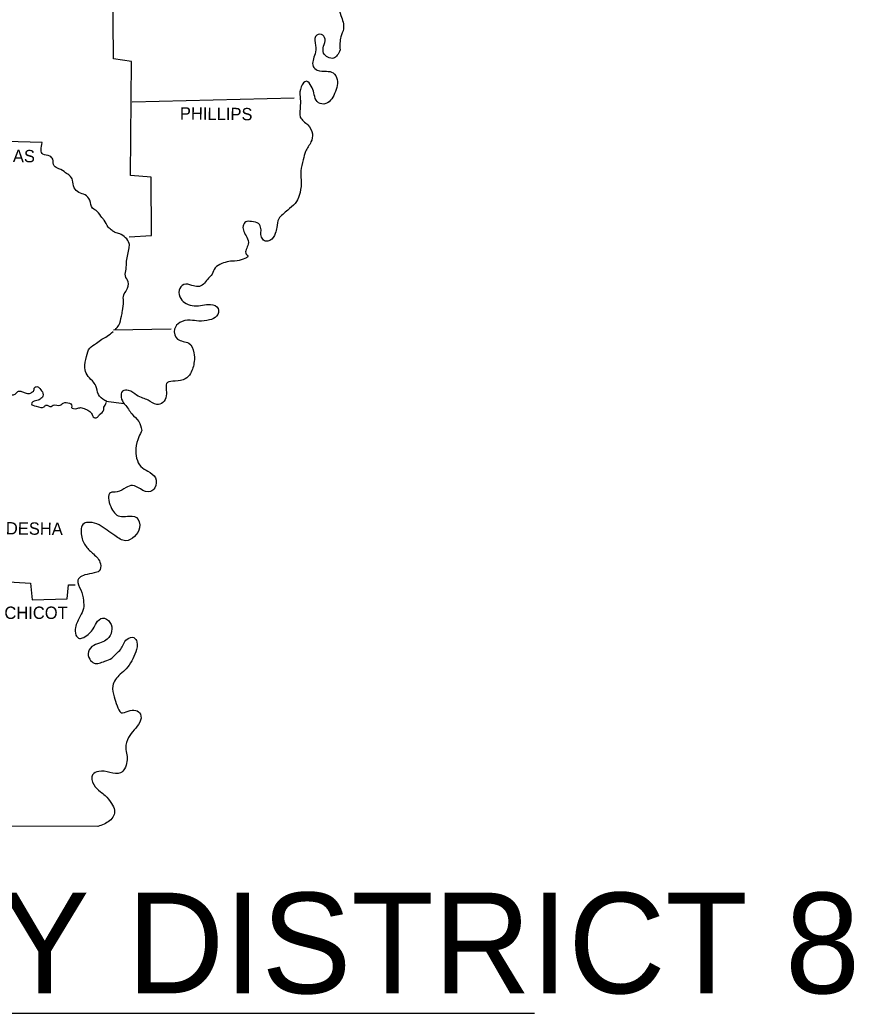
# Model space of a CAD drawing. Extents: x 1373862 to 1376999, y 1168398 to 1170455.
# Drawn here: x 1376569.3 to 1376859.3, y 1169681.4 to 1170026.9 of the extents above; entities that cross this region are included whole.
import ezdxf

# ---------------------------------------------------------------- set-up
doc = ezdxf.new("R2010")
doc.units = 0
doc.layers.add('R_Draft', color=7, linetype='Continuous')

msp = doc.modelspace()

# ---------------------------------------------------------------- linework, layer by layer
at = {"layer": 'R_Draft'}
for p, q in [((1376601.9, 1169919.1), (1376621.9, 1169919.4)), ((1376605.5, 1169893.3), (1376599.2, 1169894.1)), ((1376086.96, 1169681.4), (1376748.18, 1169681.4))]:
    msp.add_line(p, q, dxfattribs=at)
for points in [[(1376607.3, 1169951.4), (1376615.1, 1169951.9), (1376615, 1169972.2), (1376607.7, 1169972.7), (1376608.1, 1170012.4), (1376601.8, 1170013.3), (1376601.6, 1170040), (1376686.9, 1170040.6)], [(1376608.3, 1169998.3), (1376664.7, 1169999.7)], [(1376577, 1169984.2), (1376539.2, 1169985.2), (1376539, 1169972.9), (1376462.5, 1169972.6)], [(1376559.6, 1169831.7), (1376573, 1169830.9), (1376573.6, 1169825.1), (1376585.7, 1169825.5), (1376586.2, 1169830.4), (1376588.5, 1169830.4)], [(1376596.4, 1169746.3), (1376229.9, 1169746.9), (1376229.7, 1169827.8)]]:
    msp.add_lwpolyline(points, dxfattribs=at)
for points in [[(1376724, 1170115.5), (1376724.4, 1170112.6), (1376722.7, 1170109.5), (1376722.1, 1170106.4), (1376722.4, 1170103.3), (1376719.2, 1170101.6), (1376716.4, 1170099.6), (1376718, 1170097.2), (1376721, 1170095), (1376724, 1170093.3), (1376725.9, 1170091.6), (1376726.4, 1170087.5), (1376726.9, 1170084.9), (1376727.9, 1170081.3), (1376728.3, 1170078.8), (1376726.5, 1170075.8), (1376724.4, 1170075.2), (1376722.2, 1170075.9), (1376719.6, 1170076.1), (1376717.5, 1170074.1), (1376716, 1170071.3), (1376714.5, 1170068.5), (1376713.4, 1170066.1), (1376712.3, 1170063.5), (1376710.1, 1170060.5), (1376707.4, 1170060), (1376704.2, 1170059.2), (1376702.3, 1170057), (1376702.6, 1170053.3), (1376704.4, 1170050.8), (1376705.8, 1170047.7), (1376706.8, 1170045), (1376706.3, 1170041.6), (1376704.9, 1170039.1), (1376703.1, 1170037.6), (1376702.3, 1170034.4), (1376701, 1170032), (1376699.8, 1170031.2), (1376697.4, 1170031.4), (1376694.8, 1170031.9), (1376692.6, 1170031.7), (1376690.5, 1170030.6), (1376688.4, 1170031.3), (1376686.2, 1170033.7), (1376684.4, 1170035.5), (1376682.4, 1170036.2), (1376680.3, 1170035.1), (1376679.9, 1170031.8), (1376680.9, 1170028.4), (1376681.8, 1170023.8), (1376680.9, 1170021), (1376680.6, 1170016.4)], [(1376724, 1170115.5), (1376724.4, 1170112.6), (1376722.7, 1170109.5), (1376722.1, 1170106.4), (1376722.4, 1170103.3), (1376719.2, 1170101.6), (1376716.4, 1170099.6), (1376718, 1170097.2), (1376721, 1170095), (1376724, 1170093.3), (1376725.9, 1170091.6), (1376726.4, 1170087.5), (1376726.9, 1170084.9), (1376727.9, 1170081.3), (1376728.3, 1170078.8), (1376726.5, 1170075.8), (1376724.4, 1170075.2), (1376722.2, 1170075.9), (1376719.6, 1170076.1), (1376717.5, 1170074.1), (1376716, 1170071.3), (1376714.5, 1170068.5), (1376713.4, 1170066.1), (1376712.3, 1170063.5), (1376710.1, 1170060.5), (1376707.4, 1170060), (1376704.2, 1170059.2), (1376702.3, 1170057), (1376702.6, 1170053.3), (1376704.4, 1170050.8), (1376705.8, 1170047.7), (1376706.8, 1170045), (1376706.3, 1170041.6), (1376704.9, 1170039.1), (1376703.1, 1170037.6), (1376702.3, 1170034.4), (1376701, 1170032), (1376699.8, 1170031.2), (1376697.4, 1170031.4), (1376694.8, 1170031.9), (1376692.6, 1170031.7), (1376690.5, 1170030.6), (1376688.4, 1170031.3), (1376686.2, 1170033.7), (1376684.4, 1170035.5), (1376682.4, 1170036.2), (1376680.3, 1170035.1), (1376679.9, 1170031.8), (1376680.9, 1170028.4), (1376681.8, 1170023.8), (1376680.9, 1170021), (1376680.6, 1170016.4)], [(1376680.6, 1170016.4), (1376678.3, 1170013.5), (1376674.9, 1170015.3), (1376674.9, 1170017.7), (1376675.4, 1170020.2), (1376674.2, 1170021.8), (1376672.1, 1170021.1), (1376672.1, 1170018), (1376671.9, 1170015), (1376671.3, 1170010.7), (1376672.7, 1170009.4), (1376675.9, 1170009), (1376678.2, 1170008.4), (1376679.6, 1170006.1), (1376679.5, 1170003.3), (1376678.4, 1170000.6), (1376676.8, 1169998.4), (1376674.3, 1169997.6), (1376672.3, 1169998.9), (1376671.5, 1170001.5), (1376670.6, 1170003.8), (1376668.9, 1170005.5), (1376667.1, 1170003.6), (1376666.7, 1170000.1), (1376666.8, 1169997.1), (1376666.8, 1169993), (1376669.4, 1169990.3), (1376671, 1169987.2), (1376670.5, 1169984.4), (1376668.6, 1169981.1), (1376667.8, 1169978.2), (1376667, 1169974.3), (1376667.1, 1169970), (1376666.4, 1169965.8), (1376665, 1169963), (1376662.4, 1169960.7), (1376660.7, 1169959.2), (1376659.3, 1169957.7), (1376658.6, 1169954.7), (1376658.1, 1169952.6), (1376656.2, 1169950.1), (1376654.7, 1169949.9), (1376653.5, 1169950.9), (1376653.1, 1169952.6), (1376653.1, 1169954.3), (1376652.3, 1169956), (1376649.8, 1169956.7), (1376647.8, 1169956.6), (1376646.9, 1169955.2), (1376648.2, 1169951.3), (1376648.7, 1169948.8), (1376648, 1169945.4), (1376648.4, 1169945), (1376644.8, 1169943.1), (1376641.9, 1169942.8), (1376639.5, 1169942.1), (1376637.2, 1169940.6), (1376636.1, 1169938.4), (1376634.5, 1169936.6), (1376633.1, 1169934.9), (1376631.2, 1169934.1), (1376629.1, 1169934.5), (1376626.3, 1169934.8), (1376624.7, 1169932.8), (1376625.2, 1169929.9), (1376627.1, 1169928.2), (1376629.9, 1169927.4), (1376632.8, 1169927.6), (1376635.6, 1169927.9), (1376638.2, 1169926.5), (1376637.7, 1169923.8), (1376635.2, 1169922.5), (1376631.5, 1169922.1), (1376628.5, 1169922.4), (1376624.9, 1169921.6), (1376623.1, 1169919.3), (1376624.1, 1169915.8), (1376628, 1169914.4), (1376629.8, 1169911.1), (1376629.9, 1169908), (1376628.6, 1169903.9), (1376626.8, 1169902), (1376623.3, 1169901.2), (1376620.6, 1169900.7), (1376620.2, 1169896.1), (1376619, 1169893.8), (1376616.9, 1169893.1), (1376613.9, 1169894.6), (1376612.1, 1169895.3), (1376609.9, 1169896.3), (1376607.1, 1169898), (1376605, 1169897.7), (1376605.6, 1169893.3), (1376605.8, 1169893.1), (1376608.2, 1169889.8), (1376610.6, 1169887.2), (1376611.7, 1169884.1)], [(1376680.6, 1170016.4), (1376678.3, 1170013.5), (1376674.9, 1170015.3), (1376674.9, 1170017.7), (1376675.4, 1170020.2), (1376674.2, 1170021.8), (1376672.1, 1170021.1), (1376672.1, 1170018), (1376671.9, 1170015), (1376671.3, 1170010.7), (1376672.7, 1170009.4), (1376675.9, 1170009), (1376678.2, 1170008.4), (1376679.6, 1170006.1), (1376679.5, 1170003.3), (1376678.4, 1170000.6), (1376676.8, 1169998.4), (1376674.3, 1169997.6), (1376672.3, 1169998.9), (1376671.5, 1170001.5), (1376670.6, 1170003.8), (1376668.9, 1170005.5), (1376667.1, 1170003.6), (1376666.7, 1170000.1), (1376666.8, 1169997.1), (1376666.8, 1169993), (1376669.4, 1169990.3), (1376671, 1169987.2), (1376670.5, 1169984.4), (1376668.6, 1169981.1), (1376667.8, 1169978.2), (1376667, 1169974.3), (1376667.1, 1169970), (1376666.4, 1169965.8), (1376665, 1169963), (1376662.4, 1169960.7), (1376660.7, 1169959.2), (1376659.3, 1169957.7), (1376658.6, 1169954.7), (1376658.1, 1169952.6), (1376656.2, 1169950.1), (1376654.7, 1169949.9), (1376653.5, 1169950.9), (1376653.1, 1169952.6), (1376653.1, 1169954.3), (1376652.3, 1169956), (1376649.8, 1169956.7), (1376647.8, 1169956.6), (1376646.9, 1169955.2), (1376648.2, 1169951.3), (1376648.7, 1169948.8), (1376648, 1169945.4), (1376648.4, 1169945), (1376644.8, 1169943.1), (1376641.9, 1169942.8), (1376639.5, 1169942.1), (1376637.2, 1169940.6), (1376636.1, 1169938.4), (1376634.5, 1169936.6), (1376633.1, 1169934.9), (1376631.2, 1169934.1), (1376629.1, 1169934.5), (1376626.3, 1169934.8), (1376624.7, 1169932.8), (1376625.2, 1169929.9), (1376627.1, 1169928.2), (1376629.9, 1169927.4), (1376632.8, 1169927.6), (1376635.6, 1169927.9), (1376638.2, 1169926.5), (1376637.7, 1169923.8), (1376635.2, 1169922.5), (1376631.5, 1169922.1), (1376628.5, 1169922.4), (1376624.9, 1169921.6), (1376623.1, 1169919.3), (1376624.1, 1169915.8), (1376628, 1169914.4), (1376629.8, 1169911.1), (1376629.9, 1169908), (1376628.6, 1169903.9), (1376626.8, 1169902), (1376623.3, 1169901.2), (1376620.6, 1169900.7), (1376620.2, 1169896.1), (1376619, 1169893.8), (1376616.9, 1169893.1), (1376613.9, 1169894.6), (1376612.1, 1169895.3), (1376609.9, 1169896.3), (1376607.1, 1169898), (1376605, 1169897.7), (1376605.6, 1169893.3), (1376605.8, 1169893.1), (1376608.2, 1169889.8), (1376610.6, 1169887.2), (1376611.7, 1169884.1)], [(1376602.4, 1169919.1), (1376603.7, 1169920.7), (1376604.6, 1169923.8), (1376605, 1169925.7), (1376605.3, 1169929), (1376605.4, 1169931.2), (1376606.4, 1169932.8), (1376606.9, 1169935.8), (1376606, 1169937.8), (1376606.2, 1169940.2), (1376606.4, 1169942.9), (1376606.8, 1169945.3), (1376607.3, 1169947.6), (1376607.3, 1169949.1), (1376606, 1169951.1), (1376604, 1169952.4), (1376602.4, 1169952.9), (1376601.4, 1169953.6), (1376600, 1169954.8), (1376598.6, 1169957.2), (1376597.8, 1169958.1), (1376596.2, 1169960.2), (1376594.6, 1169961.4), (1376593.6, 1169964.1), (1376592, 1169966), (1376589.8, 1169966.8), (1376588.2, 1169968.5), (1376587.6, 1169971.1), (1376586.6, 1169972.7), (1376585.2, 1169973.7), (1376582.9, 1169975.1), (1376581.2, 1169976.1), (1376580.7, 1169978.4), (1376579.7, 1169979.5), (1376577.3, 1169980.1), (1376577, 1169984.2)], [(1376539, 1169932.5), (1376540.5, 1169931.5), (1376542.6, 1169931.6), (1376544, 1169932.2), (1376545.1, 1169932.1), (1376546.6, 1169931.2), (1376547.6, 1169930), (1376548.3, 1169929.1), (1376548.8, 1169927.7), (1376548.8, 1169926.4), (1376549.3, 1169924.6), (1376549.9, 1169923.9), (1376550.7, 1169922.6), (1376551.2, 1169921.4), (1376551.5, 1169920.6), (1376552.6, 1169919.3), (1376553.6, 1169919.4), (1376554.5, 1169919.3), (1376555.7, 1169918.6), (1376557.5, 1169917.2), (1376557.8, 1169916.8), (1376559, 1169914.2), (1376559.2, 1169912.6), (1376559.4, 1169910.5), (1376559.8, 1169908.5), (1376560.6, 1169906.3), (1376561, 1169904.8), (1376561.9, 1169902.7), (1376562.5, 1169901.3), (1376563.3, 1169899.5), (1376564.5, 1169897.5), (1376565, 1169896.3), (1376566.7, 1169896.4), (1376567.9, 1169896.9), (1376568.8, 1169897.7), (1376569.9, 1169897.6), (1376571.1, 1169897.2), (1376572.7, 1169896.9), (1376573.7, 1169897.5), (1376574.2, 1169897.9), (1376574.3, 1169898.8), (1376575.2, 1169899.3), (1376576.2, 1169898.6), (1376577.3, 1169897), (1376577.3, 1169896), (1376576.9, 1169895.4), (1376575.6, 1169894.6), (1376573.8, 1169894), (1376573.3, 1169893.3), (1376575, 1169892.5), (1376577.7, 1169892.3), (1376578.4, 1169892.9), (1376580.2, 1169892.4), (1376580.9, 1169892.9), (1376583.3, 1169892.8), (1376584.4, 1169893.6), (1376586.6, 1169893.5), (1376587.3, 1169893), (1376587.3, 1169892.1), (1376589.1, 1169891.7), (1376590.4, 1169892), (1376592.1, 1169891.5), (1376593.6, 1169890.7), (1376594.4, 1169889.6), (1376595.4, 1169888.4), (1376596.3, 1169888.7), (1376597, 1169889.6), (1376598.5, 1169891.2), (1376598.5, 1169892.2), (1376598.9, 1169892.9), (1376599.4, 1169893.9)], [(1376599.5, 1169894.2), (1376598.8, 1169894.5), (1376596.6, 1169896.6), (1376595.7, 1169899.6), (1376594.5, 1169901.3), (1376592.7, 1169903.4), (1376591.9, 1169905.8), (1376592.5, 1169909.8), (1376593.6, 1169912.7), (1376595.9, 1169914.4), (1376597.8, 1169915.8), (1376599.6, 1169916.8), (1376601.7, 1169918.5)], [(1376611.7, 1169884.1), (1376610.7, 1169881.8), (1376609.6, 1169877.8), (1376609.9, 1169874.4), (1376611.4, 1169871.5), (1376613.8, 1169869.9), (1376616.4, 1169867.6), (1376616.2, 1169864.1), (1376614.7, 1169862.8), (1376611.2, 1169863.7), (1376608.5, 1169864.9), (1376606.2, 1169864.2), (1376603.1, 1169862.7), (1376600.8, 1169862.4), (1376600.9, 1169857.6), (1376604, 1169854.2), (1376606.7, 1169854.2), (1376609.8, 1169853.8), (1376610.9, 1169850.2), (1376609.1, 1169847.2), (1376606.1, 1169845.7), (1376602.3, 1169847.5), (1376599.6, 1169849.4), (1376596.9, 1169851.2), (1376593.5, 1169852.1), (1376591.6, 1169851.7), (1376590.7, 1169847.5), (1376592.3, 1169843.7), (1376594.9, 1169841.1), (1376597.3, 1169837.7), (1376596.9, 1169835.2), (1376595.1, 1169834.5), (1376591.9, 1169833.8), (1376590, 1169832.8), (1376589.5, 1169832), (1376590.5, 1169828.6), (1376591.4, 1169824.9), (1376591.4, 1169822.1), (1376590.3, 1169819.5), (1376588.6, 1169815.5), (1376588.8, 1169812.9), (1376590, 1169811.7), (1376591.5, 1169812.1), (1376593.5, 1169813.5), (1376594.8, 1169815.1), (1376595.9, 1169817.1), (1376598, 1169818.8), (1376600.6, 1169817.3), (1376601.2, 1169814.2), (1376599.7, 1169811.5), (1376597.6, 1169810.3), (1376595, 1169809.3), (1376593.1, 1169807.1), (1376593.6, 1169804.5), (1376595.1, 1169803.1), (1376598.8, 1169803.8), (1376601.3, 1169804.9), (1376602.7, 1169806.3), (1376604.4, 1169808), (1376605.3, 1169809.7), (1376606.6, 1169811.5), (1376608.9, 1169812), (1376610, 1169810.5), (1376609.6, 1169807.1), (1376608.2, 1169803.9), (1376606.3, 1169801.2), (1376604.2, 1169799.3), (1376601.6, 1169795.2), (1376602.1, 1169791.4), (1376603.1, 1169788.3), (1376604.5, 1169785.9), (1376606.9, 1169786.4), (1376609.6, 1169786.7), (1376611.2, 1169785.4), (1376611, 1169782.6), (1376609, 1169779.9), (1376607.1, 1169777.3), (1376606.1, 1169773.7), (1376606.5, 1169771.2), (1376606.5, 1169768.9), (1376605.7, 1169766.4), (1376604.3, 1169765), (1376600.6, 1169765.1), (1376596.7, 1169765.5), (1376594.6, 1169764.3), (1376595, 1169760.9), (1376597.3, 1169758.4), (1376598.9, 1169757.1), (1376601.2, 1169754.3), (1376602.2, 1169752), (1376601.9, 1169750), (1376600.5, 1169748.3), (1376596.4, 1169746.3)], [(1376611.7, 1169884.1), (1376610.7, 1169881.8), (1376609.6, 1169877.8), (1376609.9, 1169874.4), (1376611.4, 1169871.5), (1376613.8, 1169869.9), (1376616.4, 1169867.6), (1376616.2, 1169864.1), (1376614.7, 1169862.8), (1376611.2, 1169863.7), (1376608.5, 1169864.9), (1376606.2, 1169864.2), (1376603.1, 1169862.7), (1376600.8, 1169862.4), (1376600.9, 1169857.6), (1376604, 1169854.2), (1376606.7, 1169854.2), (1376609.8, 1169853.8), (1376610.9, 1169850.2), (1376609.1, 1169847.2), (1376606.1, 1169845.7), (1376602.3, 1169847.5), (1376599.6, 1169849.4), (1376596.9, 1169851.2), (1376593.5, 1169852.1), (1376591.6, 1169851.7), (1376590.7, 1169847.5), (1376592.3, 1169843.7), (1376594.9, 1169841.1), (1376597.3, 1169837.7), (1376596.9, 1169835.2), (1376595.1, 1169834.5), (1376591.9, 1169833.8), (1376590, 1169832.8), (1376589.5, 1169832), (1376590.5, 1169828.6), (1376591.4, 1169824.9), (1376591.4, 1169822.1), (1376590.3, 1169819.5), (1376588.6, 1169815.5), (1376588.8, 1169812.9), (1376590, 1169811.7), (1376591.5, 1169812.1), (1376593.5, 1169813.5), (1376594.8, 1169815.1), (1376595.9, 1169817.1), (1376598, 1169818.8), (1376600.6, 1169817.3), (1376601.2, 1169814.2), (1376599.7, 1169811.5), (1376597.6, 1169810.3), (1376595, 1169809.3), (1376593.1, 1169807.1), (1376593.6, 1169804.5), (1376595.1, 1169803.1), (1376598.8, 1169803.8), (1376601.3, 1169804.9), (1376602.7, 1169806.3), (1376604.4, 1169808), (1376605.3, 1169809.7), (1376606.6, 1169811.5), (1376608.9, 1169812), (1376610, 1169810.5), (1376609.6, 1169807.1), (1376608.2, 1169803.9), (1376606.3, 1169801.2), (1376604.2, 1169799.3), (1376601.6, 1169795.2), (1376602.1, 1169791.4), (1376603.1, 1169788.3), (1376604.5, 1169785.9), (1376606.9, 1169786.4), (1376609.6, 1169786.7), (1376611.2, 1169785.4), (1376611, 1169782.6), (1376609, 1169779.9), (1376607.1, 1169777.3), (1376606.1, 1169773.7), (1376606.5, 1169771.2), (1376606.5, 1169768.9), (1376605.7, 1169766.4), (1376604.3, 1169765), (1376600.6, 1169765.1), (1376596.7, 1169765.5), (1376594.6, 1169764.3), (1376595, 1169760.9), (1376597.3, 1169758.4), (1376598.9, 1169757.1), (1376601.2, 1169754.3), (1376602.2, 1169752), (1376601.9, 1169750), (1376600.5, 1169748.3), (1376596.4, 1169746.3)]]:
    msp.add_spline(points, degree=3, dxfattribs=at)

# ---------------------------------------------------------------- texts
for s, rotation, p in [('PHILLIPS', 359.3179, (1376624.9, 1169992.2)), ('ARKANSAS', 359.2678, (1376543.2, 1169977.7)), ('DESHA', 359.3704, (1376564.4, 1169847.9))]:
    msp.add_text(s, height=4.3, rotation=rotation, dxfattribs=at).set_placement(p)
for s, height, p in [('CHICOT', 4.3, (1376563.9, 1169818.5)), ('ARKANSAS HIGHWAY DISTRICT 8', 35, (1376102, 1169688.3))]:
    msp.add_text(s, height=height, dxfattribs=at).set_placement(p)

doc.saveas('drawing.dxf')
